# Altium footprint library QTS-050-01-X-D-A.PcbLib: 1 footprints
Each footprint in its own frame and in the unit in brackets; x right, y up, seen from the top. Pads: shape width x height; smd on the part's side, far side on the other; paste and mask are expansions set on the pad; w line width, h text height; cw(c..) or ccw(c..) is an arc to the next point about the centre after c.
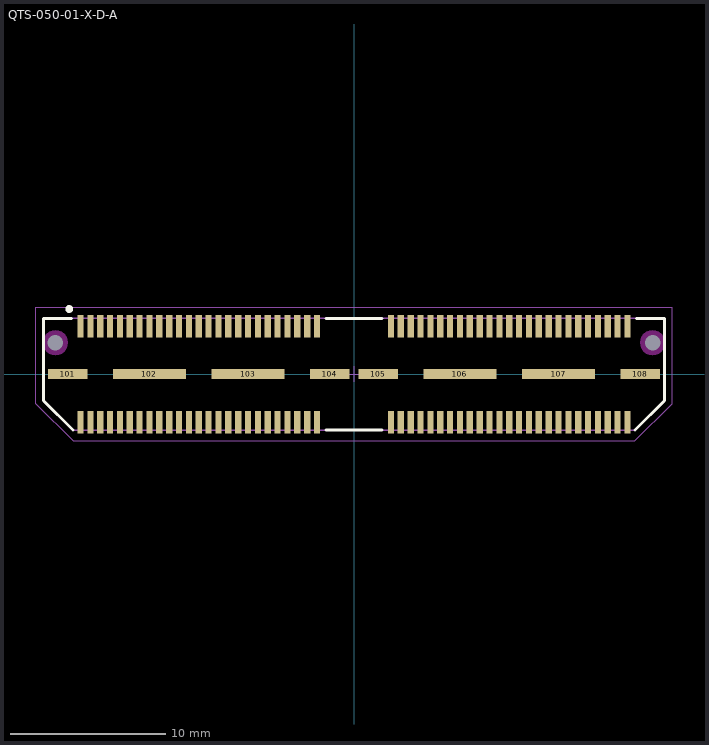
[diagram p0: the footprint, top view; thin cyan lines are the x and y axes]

## QTS-050-01-X-D-A [mm] "0.635mm pitch, 100 pin, high speed terminal strip"
height 4.27
pads (110):
  rect 0.4x1.45 smd mask+0: 1(-17.621,3.086) 2(-17.621,-3.086) 3(-16.986,3.086) 4(-16.986,-3.086) 5(-16.351,3.086) 6(-16.351,-3.086) 7(-15.716,3.086) 8(-15.716,-3.086) 9(-15.081,3.086) 10(-15.081,-3.086) 11(-14.446,3.086) 12(-14.446,-3.086) 13(-13.811,3.086) 14(-13.811,-3.086) 15(-13.176,3.086) 16(-13.176,-3.086) 17(-12.541,3.086) 18(-12.541,-3.086) 19(-11.906,3.086) 20(-11.906,-3.086) 21(-11.271,3.086) 22(-11.271,-3.086) 23(-10.636,3.086) 24(-10.636,-3.086) 25(-10.001,3.086) 26(-10.001,-3.086) 27(-9.366,3.086) 28(-9.366,-3.086) 29(-8.731,3.086) 30(-8.731,-3.086) 31(-8.096,3.086) 32(-8.096,-3.086) 33(-7.461,3.086) 34(-7.461,-3.086) 35(-6.826,3.086) 36(-6.826,-3.086) 37(-6.191,3.086) 38(-6.191,-3.086) 39(-5.556,3.086) 40(-5.556,-3.086) 41(-4.921,3.086) 42(-4.921,-3.086) 43(-4.286,3.086) 44(-4.286,-3.086) 45(-3.651,3.086) 46(-3.651,-3.086) 47(-3.016,3.086) 48(-3.016,-3.086) 49(-2.381,3.086) 50(-2.381,-3.086) 51(2.381,3.086) 52(2.381,-3.086) 53(3.016,3.086) 54(3.016,-3.086) 55(3.651,3.086) 56(3.651,-3.086) 57(4.286,3.086) 58(4.286,-3.086) 59(4.921,3.086) 60(4.921,-3.086) 61(5.556,3.086) 62(5.556,-3.086) 63(6.191,3.086) 64(6.191,-3.086) 65(6.826,3.086) 66(6.826,-3.086) 67(7.461,3.086) 68(7.461,-3.086) 69(8.096,3.086) 70(8.096,-3.086) 71(8.731,3.086) 72(8.731,-3.086) 73(9.366,3.086) 74(9.366,-3.086) 75(10.001,3.086) 76(10.001,-3.086) 77(10.636,3.086) 78(10.636,-3.086) 79(11.271,3.086) 80(11.271,-3.086) 81(11.906,3.086) 82(11.906,-3.086) 83(12.541,3.086) 84(12.541,-3.086) 85(13.176,3.086) 86(13.176,-3.086) 87(13.811,3.086) 88(13.811,-3.086) 89(14.446,3.086) 90(14.446,-3.086) 91(15.081,3.086) 92(15.081,-3.086) 93(15.716,3.086) 94(15.716,-3.086) 95(16.351,3.086) 96(16.351,-3.086) 97(16.986,3.086) 98(16.986,-3.086) 99(17.621,3.086) 100(17.621,-3.086)
  rect 2.55x0.65 smd mask+0: 101(-18.447,0) 104(-1.556,0) 105(1.556,0) 108(18.447,0)
  rect 4.7x0.65 smd mask+0: 102(-13.176,0) 103(-6.826,0) 106(6.826,0) 107(13.176,0)
  round 0.5 hole 1 unplated mask+0: 109(-19.241,2.032) 110(19.241,2.032)
Top Overlay:
  circle w0.25: c-18.35,4.2 r0.125
  lines w0.2: -18.2,3.6 -20,3.6 -20,-1.7 -18.1,-3.6 ; -1.8,-3.6 1.8,-3.6 ; -1.8,3.6 1.8,3.6 ; 18.098,-3.6 18.1,-3.6 20,-1.7 20,3.6 18.2,3.6
Keep-Out Layer:
  pour cut-out: -18.434,2.032 -18.462,2.241 -18.542,2.435 -18.67,2.603 -18.838,2.731 -19.032,2.811 -19.241,2.839 -19.45,2.811 -19.644,2.731 -19.812,2.603 -19.94,2.435 -20.02,2.241 -20.048,2.032 -20.02,1.823 -19.94,1.629 -19.812,1.461 -19.644,1.333 -19.45,1.253 -19.241,1.225 -19.032,1.253 -18.838,1.333 -18.67,1.461 -18.542,1.629 -18.462,1.823
  pour cut-out: 20.048,2.032 20.02,2.241 19.94,2.435 19.812,2.603 19.644,2.731 19.45,2.811 19.241,2.839 19.032,2.811 18.838,2.731 18.67,2.603 18.542,2.435 18.462,2.241 18.434,2.032 18.462,1.823 18.542,1.629 18.67,1.461 18.838,1.333 19.032,1.253 19.241,1.225 19.45,1.253 19.644,1.333 19.812,1.461 19.94,1.629 20.02,1.823
Mechanical 12:
  lines w0.001: -20,-1.7 -20,3.6 20,3.6 20,-1.7 18.1,-3.6 -18.1,-3.6 -20,-1.7
Mechanical 13:
  lines w0.1: -20,-1.7 -20,3.6 20,3.6 20,-1.7 18.1,-3.6 -18.1,-3.6 -20,-1.7
  text ".Designator" at 0,-0.127 h1.52
Mechanical 15:
  lines w0.05: -0.5,0 0.5,0 ; 0,-0.5 0,0.5 ; -20.5,-1.9 -20.5,4.3 20.5,4.3 20.5,-1.9 18.1,-4.3 -18.1,-4.3 -20.5,-1.9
